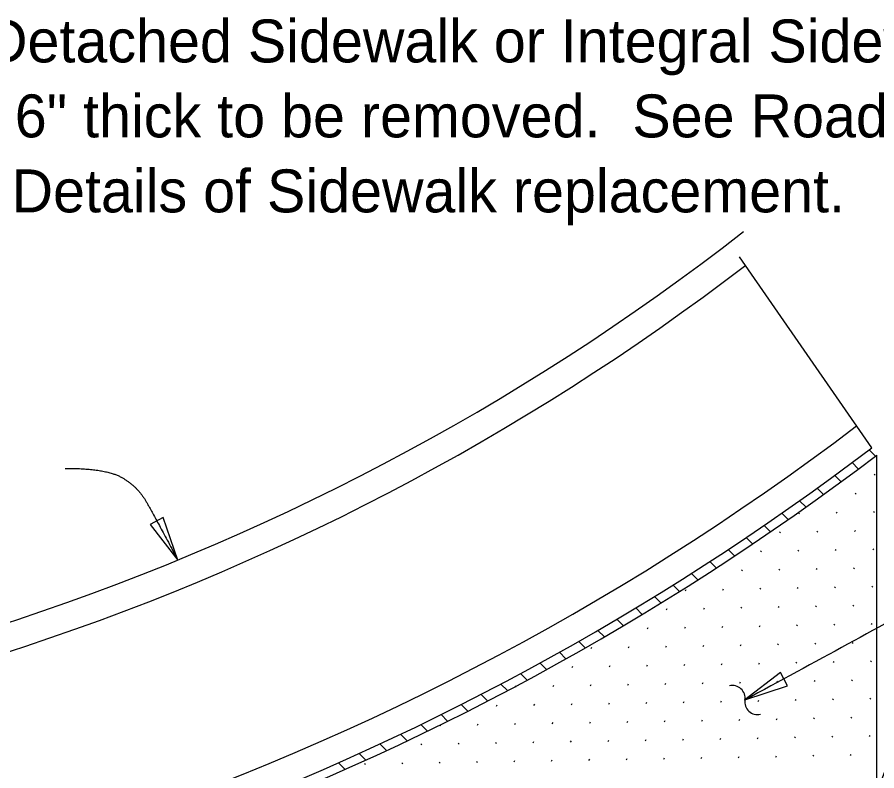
# Model space of a CAD drawing. Extents: x 21526.6 to 21598.7, y 56118.1 to 56155.9.
# Drawn here: x 21558.378 to 21562.412, y 56149.572 to 56153.11 of the extents above; entities that cross this region are included whole.
import ezdxf

# ---------------------------------------------------------------- set-up
doc = ezdxf.new("R2010")
doc.units = 0
for name, color, linetype in [('AdhocPoint_dp', 7, 'Continuous'), ('Patterning', 7, 'Continuous'), ('PlotBorder_dp', 7, 'Continuous')]:
    doc.layers.add(name, color=color, linetype=linetype)

msp = doc.modelspace()

# ---------------------------------------------------------------- linework, layer by layer
at = {"layer": 'AdhocPoint_dp'}
for p, q in [((21562.3881, 56151.0884), (21561.767, 56151.9855)), ((21562.4118, 56147.2732), (21562.4118, 56151.0541))]:
    msp.add_line(p, q, dxfattribs=at)
for radius, start, end in [(11.3394, 267.40102, 307.93264), (11.4702, 267.84731, 307.49092), (12.3856, 268.00648, 307.27295), (12.5106, 272.22541, 307.24718), (12.5523, 272.40859, 307.2387)]:
    msp.add_arc((21554.816, 56161.0472), radius, start, end, dxfattribs=at)
at = {"layer": 'Patterning'}
for p, q in [((21562.3762, 56151.0794), (21562.4058, 56151.0498)), ((21562.2955, 56151.0186), (21562.3249, 56150.9892)), ((21562.4004, 56150.9596), (21562.4036, 56150.9652)), ((21562.2142, 56150.9585), (21562.244, 56150.9287)), ((21562.1323, 56150.899), (21562.1618, 56150.8695)), ((21562.3111, 56150.8703), (21562.3143, 56150.8759)), ((21562.0498, 56150.84), (21562.0796, 56150.8103)), ((21561.9668, 56150.7817), (21561.9964, 56150.7521)), ((21562.0465, 56150.7778), (21562.0497, 56150.7834)), ((21562.2218, 56150.781), (21562.2251, 56150.7866)), ((21562.3971, 56150.7843), (21562.4004, 56150.7899)), ((21561.8831, 56150.7239), (21561.9128, 56150.6942)), ((21561.9572, 56150.6885), (21561.9605, 56150.6941)), ((21562.1325, 56150.6918), (21562.1358, 56150.6974)), ((21562.3078, 56150.695), (21562.3111, 56150.7006)), ((21561.7989, 56150.6667), (21561.8286, 56150.637)), ((21561.714, 56150.6102), (21561.7438, 56150.5804)), ((21561.868, 56150.5993), (21561.8712, 56150.6048)), ((21562.0433, 56150.6025), (21562.0465, 56150.6081)), ((21562.2186, 56150.6057), (21562.2218, 56150.6113)), ((21562.3939, 56150.609), (21562.3971, 56150.6146)), ((21561.6286, 56150.5542), (21561.6586, 56150.5242)), ((21562.1293, 56150.5165), (21562.1325, 56150.5221)), ((21562.3046, 56150.5197), (21562.3078, 56150.5253)), ((21561.5425, 56150.4988), (21561.5723, 56150.469)), ((21561.7787, 56150.51), (21561.7819, 56150.5156)), ((21561.954, 56150.5132), (21561.9572, 56150.5188)), ((21561.4559, 56150.4441), (21561.4861, 56150.4138)), ((21562.3906, 56150.4337), (21562.3939, 56150.4393)), ((21561.5141, 56150.4175), (21561.5174, 56150.4231)), ((21561.6894, 56150.4207), (21561.6927, 56150.4263)), ((21561.8647, 56150.4239), (21561.868, 56150.4295)), ((21562.04, 56150.4272), (21562.0433, 56150.4328)), ((21562.2153, 56150.4304), (21562.2186, 56150.436)), ((21561.3686, 56150.3899), (21561.3985, 56150.36)), ((21561.2807, 56150.3364), (21561.3109, 56150.3062)), ((21561.4248, 56150.3282), (21561.4281, 56150.3338)), ((21561.6001, 56150.3314), (21561.6034, 56150.337)), ((21561.7755, 56150.3347), (21561.7787, 56150.3403)), ((21561.9508, 56150.3379), (21561.954, 56150.3435)), ((21562.1261, 56150.3412), (21562.1293, 56150.3468)), ((21562.3014, 56150.3444), (21562.3046, 56150.35)), ((21561.1922, 56150.2834), (21561.2223, 56150.2534)), ((21561.3356, 56150.2389), (21561.3388, 56150.2445)), ((21561.5109, 56150.2422), (21561.5141, 56150.2478)), ((21561.6862, 56150.2454), (21561.6894, 56150.251)), ((21561.8615, 56150.2486), (21561.8647, 56150.2542)), ((21562.0368, 56150.2519), (21562.04, 56150.2575)), ((21562.2121, 56150.2551), (21562.2153, 56150.2607)), ((21562.3874, 56150.2584), (21562.3906, 56150.264)), ((21561.1031, 56150.2311), (21561.1333, 56150.2009)), ((21561.0134, 56150.1795), (21561.0436, 56150.1492)), ((21561.4216, 56150.1529), (21561.4248, 56150.1585)), ((21561.5969, 56150.1561), (21561.6001, 56150.1617)), ((21561.7722, 56150.1594), (21561.7755, 56150.165)), ((21561.9475, 56150.1626), (21561.9508, 56150.1682)), ((21562.1228, 56150.1659), (21562.1261, 56150.1715)), ((21562.2981, 56150.1691), (21562.3014, 56150.1747)), ((21560.923, 56150.1284), (21560.9533, 56150.0981)), ((21561.071, 56150.1464), (21561.0742, 56150.152)), ((21561.2463, 56150.1496), (21561.2495, 56150.1552)), ((21560.832, 56150.078), (21560.8624, 56150.0475)), ((21561.8582, 56150.0733), (21561.8615, 56150.0789)), ((21562.0335, 56150.0766), (21562.0368, 56150.0822)), ((21562.2088, 56150.0798), (21562.2121, 56150.0854)), ((21562.3842, 56150.0831), (21562.3874, 56150.0887)), ((21560.9817, 56150.0571), (21560.985, 56150.0627)), ((21561.157, 56150.0604), (21561.1603, 56150.066)), ((21561.3323, 56150.0636), (21561.3356, 56150.0692)), ((21561.5076, 56150.0669), (21561.5109, 56150.0725)), ((21561.6829, 56150.0701), (21561.6862, 56150.0757)), ((21560.7403, 56150.0282), (21560.7707, 56149.9978)), ((21562.1196, 56149.9905), (21562.1228, 56149.9961)), ((21562.2949, 56149.9938), (21562.2981, 56149.9994)), ((21560.648, 56149.9791), (21560.6787, 56149.9484)), ((21560.7171, 56149.9646), (21560.7204, 56149.9702)), ((21560.8925, 56149.9679), (21560.8957, 56149.9735)), ((21561.0678, 56149.9711), (21561.071, 56149.9767)), ((21561.2431, 56149.9743), (21561.2463, 56149.9799)), ((21561.4184, 56149.9776), (21561.4216, 56149.9832)), ((21561.5937, 56149.9808), (21561.5969, 56149.9864)), ((21561.769, 56149.9841), (21561.7722, 56149.9897)), ((21561.9443, 56149.9873), (21561.9475, 56149.9929)), ((21560.5551, 56149.9306), (21560.5856, 56149.9001)), ((21560.4615, 56149.8828), (21560.4925, 56149.8518)), ((21560.6279, 56149.8753), (21560.6311, 56149.8809)), ((21560.8032, 56149.8786), (21560.8064, 56149.8842)), ((21560.9785, 56149.8818), (21560.9817, 56149.8874)), ((21561.1538, 56149.8851), (21561.157, 56149.8907)), ((21561.3291, 56149.8883), (21561.3323, 56149.8939)), ((21561.5044, 56149.8916), (21561.5076, 56149.8972)), ((21561.6797, 56149.8948), (21561.6829, 56149.9004)), ((21561.855, 56149.898), (21561.8582, 56149.9036)), ((21562.0303, 56149.9013), (21562.0335, 56149.9069)), ((21562.2056, 56149.9045), (21562.2088, 56149.9101)), ((21562.3809, 56149.9078), (21562.3842, 56149.9134)), ((21560.3672, 56149.8357), (21560.3979, 56149.8049)), ((21560.7139, 56149.7893), (21560.7171, 56149.7949)), ((21560.8892, 56149.7926), (21560.8925, 56149.7982)), ((21561.0645, 56149.7958), (21561.0678, 56149.8014)), ((21561.2398, 56149.799), (21561.2431, 56149.8046)), ((21561.4151, 56149.8023), (21561.4184, 56149.8079)), ((21561.5904, 56149.8055), (21561.5937, 56149.8111)), ((21561.7657, 56149.8088), (21561.769, 56149.8144)), ((21561.941, 56149.812), (21561.9443, 56149.8176)), ((21562.1163, 56149.8152), (21562.1196, 56149.8208)), ((21562.2916, 56149.8185), (21562.2949, 56149.8241)), ((21560.2723, 56149.7892), (21560.3034, 56149.7581)), ((21560.3633, 56149.7828), (21560.3665, 56149.7884)), ((21560.5386, 56149.7861), (21560.5418, 56149.7917)), ((21560.1767, 56149.7433), (21560.2076, 56149.7124)), ((21561.1505, 56149.7098), (21561.1538, 56149.7154)), ((21561.3258, 56149.713), (21561.3291, 56149.7186)), ((21561.5012, 56149.7163), (21561.5044, 56149.7218)), ((21561.6765, 56149.7195), (21561.6797, 56149.7251)), ((21561.8518, 56149.7227), (21561.855, 56149.7283)), ((21562.0271, 56149.726), (21562.0303, 56149.7316)), ((21562.2024, 56149.7292), (21562.2056, 56149.7348)), ((21562.3777, 56149.7325), (21562.3809, 56149.7381)), ((21560.0804, 56149.6982), (21560.1116, 56149.667)), ((21560.274, 56149.6936), (21560.2773, 56149.6992)), ((21560.4493, 56149.6968), (21560.4526, 56149.7024)), ((21560.6246, 56149.7), (21560.6279, 56149.7056)), ((21560.7999, 56149.7033), (21560.8032, 56149.7089)), ((21560.9752, 56149.7065), (21560.9785, 56149.7121)), ((21559.9835, 56149.6537), (21560.0146, 56149.6226)), ((21561.4119, 56149.627), (21561.4151, 56149.6326)), ((21561.5872, 56149.6302), (21561.5904, 56149.6358)), ((21561.7625, 56149.6335), (21561.7657, 56149.6391)), ((21561.9378, 56149.6367), (21561.941, 56149.6423)), ((21562.1131, 56149.6399), (21562.1163, 56149.6455)), ((21562.2884, 56149.6432), (21562.2916, 56149.6488)), ((21559.8858, 56149.6099), (21559.9171, 56149.5786)), ((21560.0095, 56149.6011), (21560.0127, 56149.6066)), ((21560.1848, 56149.6043), (21560.188, 56149.6099)), ((21560.3601, 56149.6075), (21560.3633, 56149.6131)), ((21560.5354, 56149.6108), (21560.5386, 56149.6164)), ((21560.7107, 56149.614), (21560.7139, 56149.6196)), ((21560.886, 56149.6173), (21560.8892, 56149.6229)), ((21561.0613, 56149.6205), (21561.0645, 56149.6261)), ((21561.2366, 56149.6237), (21561.2398, 56149.6293))]:
    msp.add_line(p, q, dxfattribs=at)
at = {"layer": 'PlotBorder_dp'}
for points in [[(21559.1317, 56150.5612), (21559.0636, 56150.7612), (21559.0015, 56150.7276)], [(21561.7926, 56149.9047), (21561.993, 56149.9714), (21561.9599, 56150.0337)]]:
    msp.add_lwpolyline(points, close=True, dxfattribs=at)
for centre, start, end in [((21561.7341, 56149.9128), 351.6288, 103.356), ((21561.8521, 56149.8955), 171.6288, 283.356)]:
    msp.add_arc(centre, 0.0596, start, end, dxfattribs=at)
for points in [[(21563.882, 56152.2347), (21564.3729, 56152.2347), (21564.5784, 56151.9606), (21564.1103, 56151.1382), (21561.7926, 56149.9047)], [(21558.6027, 56150.9919), (21558.7926, 56150.9919), (21558.9421, 56150.9078), (21559.0261, 56150.7613), (21559.1317, 56150.5612)], [(21563.1365, 56150.3313), (21562.7743, 56150.2588), (21562.2001, 56149.0388), (21561.8851, 56147.8698), (21561.6576, 56146.9593)]]:
    msp.add_open_spline(points, degree=2, dxfattribs=at)

# ---------------------------------------------------------------- texts
for s, p in [('Existing Detached Sidewalk or Integral Sidewalk ', (21557.213, 56152.8975)), ('less than 6" thick to be removed.  See Roadway ', (21557.213, 56152.5455)), ('Plans for Details of Sidewalk replacement.', (21557.213, 56152.1935))]:
    msp.add_text(s, height=0.2016, dxfattribs=at).set_placement(p)

doc.saveas('drawing.dxf')
